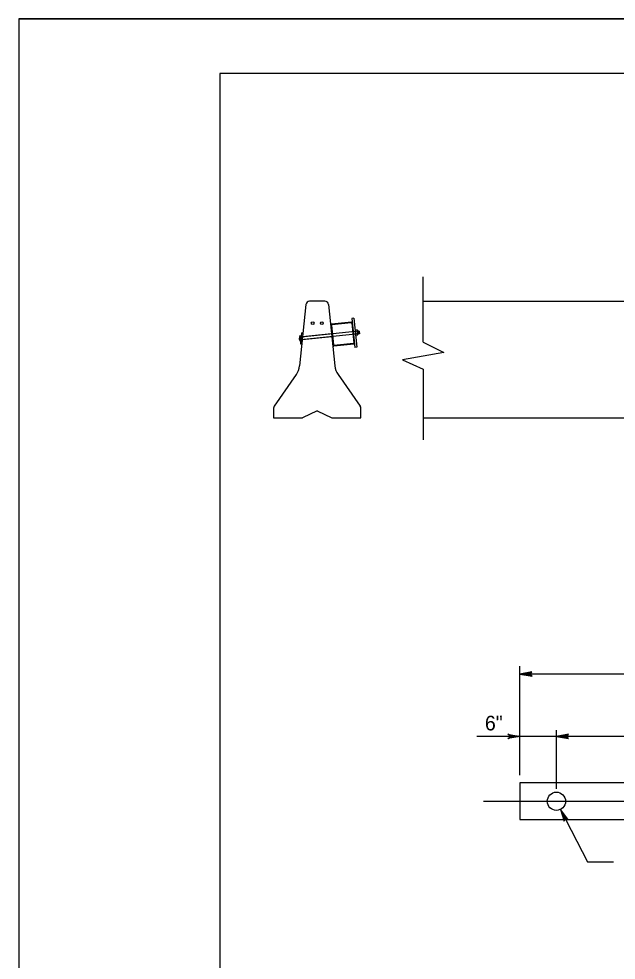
# Model space of a CAD drawing. Extents: x 499881 to 500993, y 499985 to 500645.
# Drawn here: x 499944.8 to 500108.7, y 500387 to 500645 of the extents above; entities that cross this region are included whole.
import ezdxf

# ---------------------------------------------------------------- set-up
doc = ezdxf.new("R2010")
doc.units = 0
for name, color, linetype in [('1', 7, 'Continuous'), ('2', 7, 'Continuous'), ('3', 7, 'Continuous'), ('41', 7, 'Continuous'), ('5', 7, 'Continuous')]:
    doc.layers.add(name, color=color, linetype=linetype)

msp = doc.modelspace()

# ---------------------------------------------------------------- linework, layer by layer
at = {"layer": '1'}
for p, q in [((499944.83, 500645), (500993, 500645)), ((500000, 500630), (500000, 500000)), ((500990, 500630), (500000, 500630))]:
    msp.add_line(p, q, dxfattribs=at)
at = {"layer": '2'}
for points in [[(500082.33, 500465.37), (500085.65, 500464.79), (500084.86, 500465.37), (500085.63, 500465.95), (500082.33, 500465.37), (500082.55, 500465.38), (500085.56, 500464.83), (500084.79, 500465.38), (500085.5, 500465.91), (500082.67, 500465.39), (500082.78, 500465.37), (500085.36, 500464.91), (500084.78, 500465.38), (500085.37, 500465.83), (500082.83, 500465.37), (500082.94, 500465.39), (500085.19, 500464.98), (500084.75, 500465.37), (500085.2, 500465.78), (500083.26, 500465.39), (500083.45, 500465.39), (500085.03, 500465.07), (500084.72, 500465.36), (500085.05, 500465.69), (500083.48, 500465.37), (500083.66, 500465.36), (500084.85, 500465.16), (500084.62, 500465.39), (500084.86, 500465.62), (500083.82, 500465.37), (500083.99, 500465.36), (500084.7, 500465.22), (500084.58, 500465.38), (500084.78, 500465.56), (500084.08, 500465.37), (500084.54, 500465.26), (500084.47, 500465.39), (500084.68, 500465.52), (500084.19, 500465.39), (500084.5, 500465.31), (500084.37, 500465.41), (500084.52, 500465.47), (500084.37, 500465.38), (500084.45, 500465.36)], [(500082.33, 500448.3), (500079, 500447.71), (500079.8, 500448.3), (500079.02, 500448.88), (500082.33, 500448.3), (500082.11, 500448.31), (500079.1, 500447.76), (500079.86, 500448.31), (500079.16, 500448.83), (500081.99, 500448.32), (500081.88, 500448.3), (500079.3, 500447.84), (500079.88, 500448.31), (500079.28, 500448.76), (500081.83, 500448.3), (500081.72, 500448.32), (500079.46, 500447.91), (500079.9, 500448.3), (500079.45, 500448.71), (500081.39, 500448.32), (500081.21, 500448.32), (500079.63, 500448), (500079.94, 500448.29), (500079.61, 500448.62), (500081.17, 500448.3), (500081, 500448.29), (500079.81, 500448.09), (500080.04, 500448.32), (500079.79, 500448.55), (500080.83, 500448.3), (500080.67, 500448.28), (500079.95, 500448.15), (500080.07, 500448.31), (500079.88, 500448.49), (500080.58, 500448.3), (500080.11, 500448.19), (500080.18, 500448.32), (500079.98, 500448.45), (500080.46, 500448.32), (500080.16, 500448.24), (500080.28, 500448.34), (500080.14, 500448.4), (500080.28, 500448.31), (500080.21, 500448.29)], [(500092.34, 500448.3), (500095.67, 500447.71), (500094.87, 500448.3), (500095.65, 500448.88), (500092.34, 500448.3), (500092.56, 500448.31), (500095.57, 500447.76), (500094.81, 500448.31), (500095.52, 500448.83), (500092.68, 500448.32), (500092.79, 500448.3), (500095.37, 500447.84), (500094.79, 500448.31), (500095.39, 500448.76), (500092.85, 500448.3), (500092.96, 500448.32), (500095.21, 500447.91), (500094.77, 500448.3), (500095.22, 500448.71), (500093.28, 500448.32), (500093.46, 500448.32), (500095.04, 500448), (500094.74, 500448.29), (500095.07, 500448.62), (500093.5, 500448.3), (500093.68, 500448.29), (500094.86, 500448.09), (500094.63, 500448.32), (500094.88, 500448.55), (500093.84, 500448.3), (500094.01, 500448.28), (500094.72, 500448.15), (500094.6, 500448.31), (500094.8, 500448.49), (500094.09, 500448.3), (500094.56, 500448.19), (500094.49, 500448.32), (500094.69, 500448.45), (500094.21, 500448.32), (500094.51, 500448.24), (500094.39, 500448.34), (500094.53, 500448.4), (500094.39, 500448.31), (500094.46, 500448.29)], [(500093.48, 500428.29), (500094.45, 500425.06), (500094.62, 500426.03), (500095.49, 500425.6), (500093.48, 500428.29), (500093.59, 500428.09), (500094.45, 500425.16), (500094.6, 500426.09), (500095.38, 500425.69), (500093.65, 500427.99), (500093.69, 500427.89), (500094.44, 500425.38), (500094.59, 500426.1), (500095.26, 500425.77), (500093.71, 500427.84), (500093.77, 500427.75), (500094.42, 500425.55), (500094.57, 500426.12), (500095.14, 500425.9), (500093.92, 500427.46), (500094, 500427.3), (500094.42, 500425.74), (500094.55, 500426.15), (500094.99, 500426), (500094, 500427.26), (500094.07, 500427.1), (500094.42, 500425.94), (500094.53, 500426.25), (500094.84, 500426.13), (500094.15, 500426.95), (500094.21, 500426.8), (500094.41, 500426.1), (500094.5, 500426.28), (500094.75, 500426.18), (500094.27, 500426.73), (500094.38, 500426.26), (500094.46, 500426.38), (500094.67, 500426.25), (500094.34, 500426.63), (500094.41, 500426.32), (500094.44, 500426.48), (500094.56, 500426.38), (500094.41, 500426.47), (500094.43, 500426.39)]]:
    msp.add_lwpolyline(points, dxfattribs=at)
at = {"layer": '3'}
for p, q in [((500055.81, 500556.39), (500055.81, 500574.24)), ((500028.81, 500567.57), (500024.61, 500567.57)), ((500055.81, 500567.57), (500198.81, 500567.57)), ((500023.61, 500566.67), (500021.85, 500549.86)), ((500029.8, 500566.67), (500031.56, 500549.86)), ((500036.09, 500561.83), (500030.62, 500561.26)), ((500036.73, 500562.9), (500036.23, 500562.85)), ((500036.23, 500562.85), (500037.07, 500554.89)), ((500036.73, 500562.9), (500037.57, 500554.95)), ((500037.11, 500559.3), (500022.3, 500557.75)), ((500030.4, 500560.98), (500030.97, 500555.51)), ((500030.59, 500560.94), (500031.15, 500555.59)), ((500036.05, 500561.64), (500030.7, 500561.08)), ((500036.18, 500561.53), (500036.74, 500556.18)), ((500037.63, 500559.73), (500037.13, 500559.68)), ((500037.67, 500559.36), (500037.17, 500559.3)), ((500037.71, 500559.55), (500037.83, 500558.43)), ((500038.23, 500559.42), (500037.73, 500559.36)), ((500037.87, 500559.25), (500037.92, 500558.75)), ((500037.98, 500559.39), (500038.06, 500558.64)), ((500038.12, 500559.28), (500038.17, 500558.78)), ((500038.23, 500559.42), (500038.31, 500558.67)), ((500021.96, 500558.21), (500022.15, 500556.44)), ((500022.3, 500557.75), (500022.01, 500557.72)), ((500022.3, 500557.75), (500022.09, 500557.72)), ((500022.09, 500556.97), (500022.17, 500556.98)), ((500022.42, 500558.93), (500022.11, 500555.95)), ((500022.22, 500556.98), (500022.17, 500556.98)), ((500037.19, 500558.55), (500022.22, 500556.98)), ((500022.22, 500557.01), (500022.59, 500556.97)), ((500022.31, 500557.88), (500022.69, 500557.84)), ((500022.42, 500558.93), (500022.8, 500558.9)), ((500030.73, 500557.81), (500022.59, 500556.96)), ((500030.64, 500558.68), (500022.69, 500557.85)), ((500037.75, 500558.61), (500037.25, 500558.56)), ((500037.79, 500558.24), (500037.29, 500558.18)), ((500038.31, 500558.67), (500037.81, 500558.62)), ((500022.11, 500555.95), (500022.48, 500555.91)), ((500036.72, 500555.86), (500031.24, 500555.29)), ((500036.63, 500556.04), (500031.29, 500555.48)), ((500037.57, 500554.95), (500037.07, 500554.89)), ((500055.81, 500556.39), (500061.42, 500553.51)), ((500061.42, 500553.51), (500050.08, 500551.48)), ((500050.08, 500551.48), (500055.81, 500548.94)), ((500055.81, 500548.94), (500055.81, 500529.58)), ((500020.97, 500547.51), (500014.89, 500538.83)), ((500032.44, 500547.51), (500038.53, 500538.83)), ((500014.71, 500538.26), (500014.71, 500535.58)), ((500026.71, 500537.58), (500022.71, 500535.58)), ((500026.71, 500537.58), (500030.7, 500535.58)), ((500038.71, 500535.58), (500038.71, 500538.26)), ((500014.71, 500535.58), (500022.71, 500535.58)), ((500030.7, 500535.58), (500038.71, 500535.58)), ((500055.81, 500535.58), (500198.81, 500535.58)), ((500082.33, 500437.7), (500082.33, 500467.55)), ((500322.33, 500465.37), (500082.33, 500465.37)), ((500082.33, 500448.3), (500070.51, 500448.3)), ((500092.34, 500448.3), (500082.33, 500448.3)), ((500092.34, 500433.95), (500092.34, 500449.99)), ((500177.33, 500448.3), (500092.34, 500448.3)), ((500082.33, 500435.53), (500082.33, 500425.53)), ((500322.33, 500435.53), (500082.33, 500435.53)), ((500093.49, 500428.29), (500100.83, 500413.95)), ((500082.33, 500425.53), (500322.33, 500425.53)), ((500100.83, 500413.95), (500108.02, 500413.95))]:
    msp.add_line(p, q, dxfattribs=at)
for centre, radius in [((500025.46, 500561.57), 0.375), ((500027.95, 500561.57), 0.375), ((500092.34, 500430.52), 2.5)]:
    msp.add_circle(centre, radius, dxfattribs=at)
for centre, radius, start, end in [((500024.61, 500566.57), 1, 90, 174.0136), ((500028.81, 500566.57), 1, 5.9864, 90), ((500036.12, 500561.58), 0.25, 5.9864, 95.9864), ((500030.64, 500561.01), 0.25, 95.9864, 185.9864), ((500030.71, 500560.95), 0.125, 95.9864, 185.9864), ((500036.06, 500561.51), 0.125, 5.9864, 95.9864), ((500037.41, 500559.52), 0.323, 150.4975, 221.4763), ((500038.35, 500559.05), 1.21, 167.8349, 204.1389), ((500037.39, 500559.52), 0.323, 330.497, 41.4758), ((500036.57, 500558.86), 1.21, 347.8344, 24.1384), ((500023.38, 500557.46), 1.6, 152.1575, 219.8428), ((500037.53, 500558.4), 0.323, 150.4975, 221.4763), ((500037.51, 500558.4), 0.323, 330.497, 41.4758), ((500031.22, 500555.54), 0.25, 185.9864, 275.9864), ((500031.27, 500555.61), 0.125, 185.9864, 275.9864), ((500036.62, 500556.17), 0.125, 275.9864, 5.9864), ((500036.69, 500556.11), 0.25, 275.9864, 5.9864), ((500016.88, 500550.38), 5, 324.969, 354.0136), ((500036.53, 500550.38), 5, 185.9864, 215.0335), ((500015.71, 500538.26), 1, 144.969, 180), ((500037.71, 500538.26), 1, 0, 35.0335)]:
    msp.add_arc(centre, radius, start, end, dxfattribs=at)
at = {"layer": '41'}
msp.add_lwpolyline([(499944.83, 499985), (500993, 499985), (500993, 500645), (499944.83, 500645)], close=True, dxfattribs=at)
msp.add_arc((500023.17, 500557.46), 1.6, 151.6724, 151.7004, dxfattribs=at)
at = {"layer": '5'}
msp.add_line((500072.33, 500430.53), (500332.33, 500430.53), dxfattribs=at)

# ---------------------------------------------------------------- texts
at = {"layer": '3'}
msp.add_text('6"', height=4, dxfattribs=at).set_placement((500072.72, 500449.94))

doc.saveas('drawing.dxf')
